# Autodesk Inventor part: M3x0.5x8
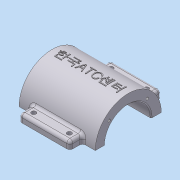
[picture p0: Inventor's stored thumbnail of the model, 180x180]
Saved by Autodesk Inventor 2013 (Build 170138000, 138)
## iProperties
Company: 한국ATC센터
Created: 2009-02
Part Number: M3x0.5x8
Document SubType Name: Modeling
Designer: KYOUNG IL JANG
Density: 2.71 g/cm^3
Mass: 199.244 g
Surface Area: 195.422 cm^2
Volume: 73.5218 cm^3
Material: 알루미늄-6061
Vendor: CBT Solutions
Author: KYOUNG IL JANG
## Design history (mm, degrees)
sketch "스케치1"
  geometry: L1 (-45, 40)-(45, 40); L2 (45, 40)-(45, -40); L3 (45, -40)-(-45, -40); L4 (-45, -40)-(-45, 40); 3 further points
  constraints: 8 end point, 2 midpoint, 2 parallel, 1 horizontal, 1 horizontal alignment, 1 perpendicular, 1 vertical alignment
  dimensions: "d0" = 90 distance of L2.end L3.end; "d1" = 80 distance of L1.end L2.end
extrude "돌출1" new body sketch "스케치1" distance "d2" = 10; taper "d3" = 0 deg
sketch "스케치2"
  geometry: L1 (40, 0)-(-40, 0) reference; C1 r 32.5 at (0, 80); 2 further points
  constraints: 1 centre point, 1 midpoint, 1 vertical alignment
  dimensions: "d4" = 65 diameter of C1; "d5" = 80 distance from line of C1.centre L1
extrude "돌출2" join sketch "스케치2" stored distance "d6" = 75; taper "d7" = 0 deg
sketch "스케치3"
  geometry: L1 (-7.5, -20)-(7.5, -20); L2 (7.5, 20)-(-7.5, 20); A1 r 20 centre (7.5, 0) between (7.5, -20) and (7.5, 20); A2 r 20 centre (-7.5, 0) between (-7.5, 20) and (-7.5, -20); 2 further points
  constraints: 4 end point, 4 point on circle, 4 tangent, 2 centre point, 1 horizontal, 1 horizontal alignment, 1 midpoint, 1 parallel, 1 vertical alignment
  dimensions: "d8" = 20 radius of A2; "d9" = 55 dimension on A1 A2
extrude "돌출3" join sketch "스케치3" stored distance "d10" = 75; taper "d11" = 0 deg
fillet "모깎기1" dims "d12" = 10
sketch "스케치4"
  geometry: L1 (-45, 0)-(-45, 10) reference; L2 (37.5, 47.5)-(-37.5, 47.5) reference; L3 (-45, 10)-(-27.513, 47.5); 1 further point
  constraints: 2 end point, 1 point on line
  dimensions: "d13" = 25 deg angle of L3 L1
sketch "스케치5"
  geometry: L1 (-40, 0)-(-40, 10) reference; L2 (-40, 10)-(-22.912, 56.95); 2 further points
  constraints: 2 end point, 2 other
  dimensions: "d14" = 20 deg angle of L2 L1
feature "리브1" dims "d15" = 1, "d16" = 6, "d17" = 0
feature "리브2" dims "d18" = 1, "d19" = 6, "d20" = 0
fillet "모깎기2" dims "d21" = 3
fillet "모깎기3" dims "d22" = 3
fillet "모깎기4" dims "d23" = 3
fillet "모깎기5" dims "d24" = 3
fillet "모깎기6" dims "d25" = 3
fillet "모깎기7" dims "d26" = 3
fillet "모깎기8" dims "d27" = 3
sketch "스케치6"
  geometry: A1 r 10 centre (35, -30) between (35, -40) and (45, -30) reference; 1 further point
hole "구멍1" sketch "스케치6" at (35, -30) diameter "d28" = 10; stored, may be unused: countersink angle "d32" = 90 deg, drill point angle "d34" = 118 deg; dims "d29" = 6, "d30" = 4, "d31" = 2, "d33" = 8
hole "구멍2" diameter "d37" = 45; stored, may be unused: countersink angle "d41" = 90 deg, drill point angle "d43" = 118 deg; dims "d35" = 10, "d36" = 10, "d38" = 6, "d39" = 4, "d40" = 2, "d42" = 8
sketch "스케치7"
  geometry: C1 r 22.5 at (0, 0) reference; 2 further points
  dimensions: "d44" = 135 deg dimension on C1.centre point (-18.738, 18.738) point (80, 0); "d45" = 26.5 distance of point (-18.738, 18.738) C1.centre
hole "구멍3" sketch "스케치7" at (-18.738, 18.738) diameter "d46" = 2.459; stored, may be unused: countersink angle "d50" = 90 deg, drill point angle "d52" = 118 deg; dims "d47" = 8, "d48" = 4, "d49" = 2, "d51" = 10
node "작업 평면1"
chamfer "모따기1" distance "d69" = 1; stored, may be unused: second distance "d70" = 2, angle "d71" = 45 deg
sketch "스케치9"
  geometry: L1 (-31.623, 87.5)-(-45, 87.5); L2 (-45, 87.5)-(-45, 72.5); L3 (-45, 72.5)-(-31.623, 72.5); A1 r 32.5 centre (0, 80) between (-31.623, 87.5) and (-31.623, 72.5) reference; 1 further point
  constraints: 6 end point, 2 parallel, 2 point on circle, 1 horizontal, 1 perpendicular
  dimensions: "d73" = 15 distance of L1.end L2.end; "d74" = 45 distance from line of A1.centre L2
extrude "돌출5" join sketch "스케치9" stored distance "d75" = 50; taper "d76" = 0 deg
fillet "모깎기10" dims "d77" = 3
fillet "모깎기11" dims "d78" = 3
sketch "스케치10"
  geometry: L1 (100.378, 66.389)-(0, 66.389); L2 (0, 66.389)-(0, -76.978); L3 (0, -76.978)-(100.378, -76.978); L4 (100.378, -76.978)-(100.378, 66.389); C1 r 32.5 at (0, 0) reference; 1 further point
  constraints: 8 end point, 2 parallel, 1 horizontal, 1 perpendicular, 1 point on line
extrude "돌출6" cut sketch "스케치10" stored distance "d79" = 10; taper "d80" = 0 deg
sketch "스케치11"
  geometry: C1 r 1.621 at (4.5, 4) reference; C2 r 1.621 at (39.5, 4) reference; 1 further point
hole "구멍5" sketch "스케치11" at (39.5, 4), (4.5, 4) diameter "d81" = 4.5; stored, may be unused: countersink angle "d85" = 90 deg, drill point angle "d87" = 118 deg; dims "d82" = 6, "d83" = 4, "d84" = 2, "d86" = 8
node "작업 평면2"
sketch "스케치12"
  geometry: 2 further points
  constraints: 1 coincident, 1 other
feature "엠보싱1" sketch "스케치12" dims "d8" = 20, "d9" = 55, "d88" = 0.5, "d89" = 0
node "솔리드1"
mirror "대칭1"
mirror "대칭2"
mirror "대칭3"
mirror "대칭4"
pattern_circular "원형 패턴1" dims angle "d54" = 360 deg
mirror "대칭5"
mirror "대칭6"
mirror "대칭7"
node "참조1"
node "참조2"
other parameters: "d56" = -117
